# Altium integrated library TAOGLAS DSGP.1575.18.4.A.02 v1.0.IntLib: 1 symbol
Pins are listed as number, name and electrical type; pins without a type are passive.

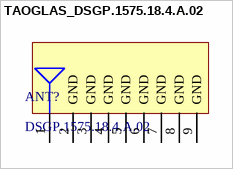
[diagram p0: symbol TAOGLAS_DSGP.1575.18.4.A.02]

## TAOGLAS_DSGP.1575.18.4.A.02
designator ANT?, comment DSGP.1575.18.4.A.02
GPS L1 / GALILEO E1 1575MHz SMD 18*18*4mm Ceramic Patch SMD Antenna; ComponentLibStatus: Created; MFG: Taoglas; Temp_Low: -45C; Temp_High: +85C
footprint TAOGLAS_DSGP.1575.18.4.A.02 (GPS L1 / GALILEO E1 1575MHz SMD 18*18*4mm Ceramic Patch SMD Antenna)
pins: 1 RF, 2 GND, 3 GND, 4 GND, 5 GND, 6 GND, 7 GND, 8 GND, 9 GND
